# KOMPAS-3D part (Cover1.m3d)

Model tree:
1. Plane XY
2. Plane ZX
3. Plane ZY
4. X Axis
5. Y Axis
6. Z Axis
7. Origin
8. Sketch:1
9. Extrude:1
     Wall Thickness 1 = 1; Wall Thickness 2 = 1; Distance 1 = 40; Distance 2 = 10
10. Sketch:2
11. Cut-Extrude:1
     Wall Thickness 1 = 1; Wall Thickness 2 = 1; Distance 2 = 10; Distance 1 = 40
12. Circular Pattern:1  (with: Cut-Extrude:1)  (labels: Instance ( 1, 1 );; Instance ( 1, 2 );; Instance ( 1, 3 );; Instance ( 1, 4 );)
     N 1 = 1; Spacing 1 = 10; N 2 = 6; Spacing 2 = 360
13. Sketch:3
14. Cut-Extrude:2
     Wall Thickness 1 = 1; Wall Thickness 2 = 1; Distance 2 = 10; Distance 1 = 40
15. Sketch:4
16. Extrude:2
     Wall Thickness 1 = 1; Wall Thickness 2 = 1; Distance 1 = 10; Distance 2 = 50
17. Fillet:1
     Radius = 3

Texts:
  Steel DIN 17102
  Three Point Plane
  Plane at Angle
  Line and Point Plane
  Axis through Two Vertices
  Axis of Feature
  Axis of Conical Surface
  Axis through Edge
  Trim by Surface
  Trim by Sketch
  Feature with No History
  Intersection Axis of Two Planes
  Two Line Plane
  Line and Face Plane
  Bend by line
  Hole in sheet body
  Cut in sheet body
  Point in CM
  Linear Dimension from Line to Point
  Surface Finish Symbol
  Geometric Tolerance Symbol
  Bend by sketch
  Arc of Circle
  Junction of curves
  Array by nodes of sketch
  Leader #1
  Leader #2
  Leader #3
  Shape Deviations and Datum
  Node point number
  Mark of coordination axis
  Node point designation
  Mark/Reference designation with leader
  Mark/reference designation on line
  Mark/Reference designation without leader
  Flange_Diam-30
  Instance ( 1, 1 );
  Instance ( 1, 2 );
  Instance ( 1, 3 );
  Instance ( 1, 4 );
  Instance ( 1, 5 );
  Instance ( 1, 6 );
